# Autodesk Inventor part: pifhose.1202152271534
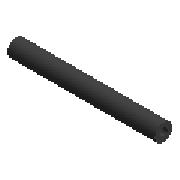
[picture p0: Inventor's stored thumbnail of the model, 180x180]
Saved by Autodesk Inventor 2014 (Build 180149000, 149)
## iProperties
NAME: PIPING: Parker Hydraulic Hose - No Skive
DATA: <meta><inlinegroups number="1" deflen="12.7"></inlinegroups><connections number="2"></connections><angles><a>3.14159265358979</a></angles></meta>
Company: Autodesk, Inc.
Created: 2008-01
Material: Rubber
Description: Hose
Document SubType Name: Modeling
Standard: Parker
Designer: Autodesk, Inc.
Manufacturer: Parker
Language: en-US
Size Designation: 1/2 - 5
Categories: <MemberInstance><Categories><Category DisplayName="Tube &amp; Pipe" InternalName="4347fa0f-2144-441d-94cd-e3e15c92b736" Mnemonic="TUBEANDPIPE"><CategoryParamete
Stock Number: Parker Hydraulic Hose - No Skive 1/2
Density: 0.93 g/cm^3
Mass: 286.153 g
Surface Area: 1280.96 cm^2
Volume: 307.691 cm^3
Appearance: Rubber (Black)
L: 45.614 in
PL: 45.614 in
RPL: 45.625 in
OPL: 48.014 in
ROPL: 48.125 in
Author: Autodesk, Inc.
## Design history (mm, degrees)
sketch "3D Sketch1" dims "d4" = 10, "d5" = 10
workpoint "Work Point3"
workpoint "Work Point4"
workplane "Work Plane1"
sketch "Sketch2"
  geometry: C1 r 11.176 at (0, 0); C2 r 6.35 at (0, 0); 1 further point
  constraints: 2 centre point
workpoint "Work Point5"
sweep "Sweep1" dims "d6" = 0
body "Solid1"
other parameters: "ID" = 12.7 [user parameter], "OD" = 22.352 [user parameter], "L" = 1158.5956 (= PL) [user parameter], "PL" = 1158.5956 [user parameter; used in 1 equation term], "Size_Designation" = 5 [user parameter], "RPL" = 1158.875 [user parameter], "OPL" = 1219.5556 [user parameter], "ROPL" = 1222.375 [user parameter]
